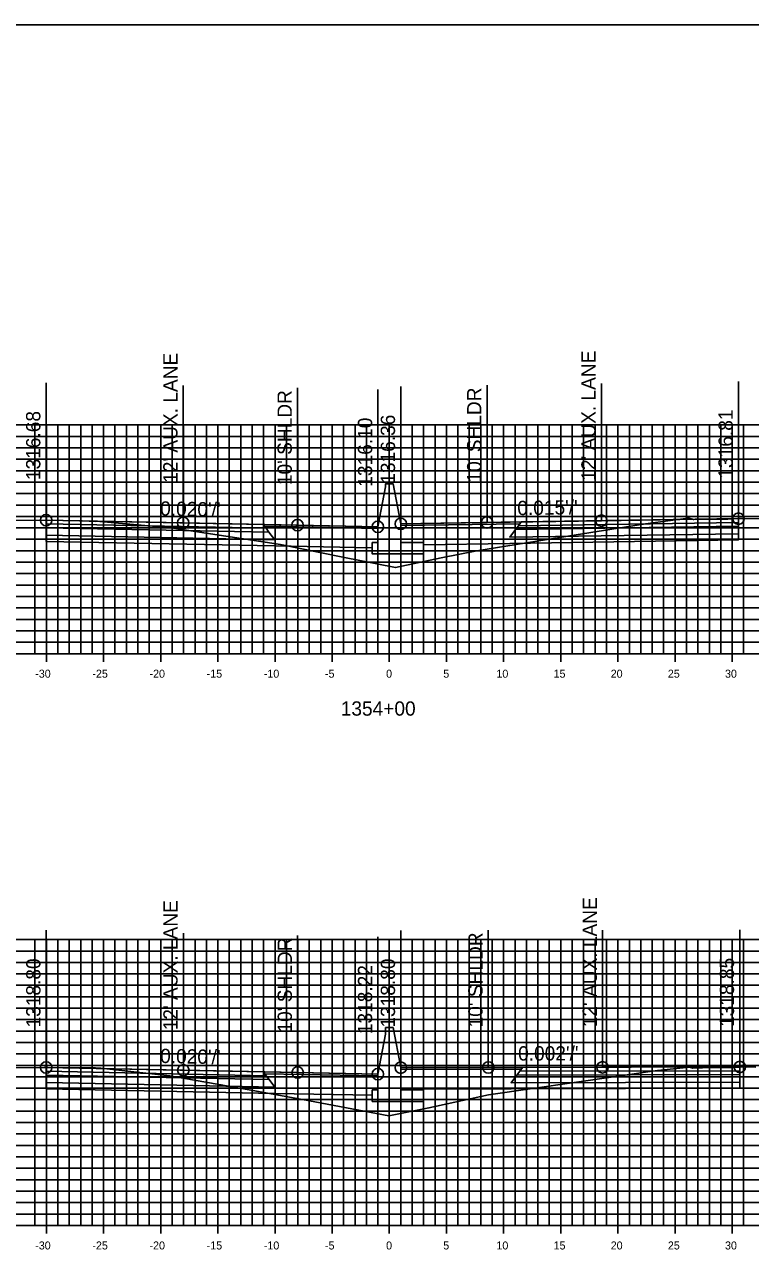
# Model space of a CAD drawing. Extents: x 674939 to 678919, y 750652 to 765176.
# Drawn here: x 678706.6 to 678770.1, y 753564.4 to 753672.6 of the extents above; entities that cross this region are included whole.
import ezdxf

# ---------------------------------------------------------------- set-up
doc = ezdxf.new("R2010")
doc.units = 0
for name, color, linetype in [('R_Alt Surface', 7, 'Continuous'), ('R_Axis', 7, 'Continuous'), ('R_Axis Annot', 7, 'Continuous'), ('R_Exist Surface', 7, 'Continuous'), ('R_Fin Surface', 7, 'Continuous'), ('R_Grid', 7, 'Continuous'), ('R_No Plot', 7, 'Continuous'), ('R_Proposed Road', 7, 'Continuous'), ('R_Xsect Elev', 7, 'Continuous'), ('R_Xsect Slope', 7, 'Continuous')]:
    doc.layers.add(name, color=color, linetype=linetype)

msp = doc.modelspace()

# ---------------------------------------------------------------- linework, layer by layer
at = {"layer": 'R_Alt Surface'}
for points in [[(678708.5, 753628.9), (678708.5, 753628.57), (678728, 753628.18), (678727.75, 753628.52)], [(678769.08, 753628.7), (678769.08, 753628.04), (678749.08, 753627.73), (678749.58, 753628.4)], [(678769.08, 753629.03), (678769.08, 753628.7), (678749.58, 753628.4), (678749.83, 753628.73)], [(678708.5, 753628.57), (678708.5, 753627.91), (678728.5, 753627.51), (678728, 753628.18)], [(678708.51, 753581.03), (678708.51, 753580.7), (678728.01, 753580.31), (678727.76, 753580.64)], [(678769.19, 753581.08), (678769.19, 753580.75), (678749.69, 753580.7), (678749.94, 753581.04)], [(678708.51, 753580.7), (678708.51, 753580.04), (678728.51, 753579.64), (678728.01, 753580.31)], [(678769.19, 753580.75), (678769.19, 753580.09), (678749.19, 753580.03), (678749.69, 753580.7)]]:
    msp.add_lwpolyline(points, close=True, dxfattribs=at)
for points in [[(678708.5, 753627.91), (678708.5, 753627.37), (678728.5, 753626.97), (678737.03, 753626.8)], [(678769.08, 753628.04), (678769.08, 753627.5), (678749.08, 753627.19), (678741.53, 753627.07)], [(678708.51, 753580.04), (678708.51, 753579.5), (678728.51, 753579.1), (678737.03, 753578.93)], [(678769.19, 753580.09), (678769.19, 753579.55), (678749.19, 753579.49), (678741.53, 753579.47)], [(678739.53, 753579.46), (678741.53, 753579.47)]]:
    msp.add_lwpolyline(points, dxfattribs=at)
at = {"layer": 'R_Axis'}
for p, q in [((678708.53, 753616.85), (678708.53, 753618.25)), ((678713.53, 753616.85), (678713.53, 753618.25)), ((678718.53, 753616.85), (678718.53, 753618.25)), ((678723.53, 753616.85), (678723.53, 753618.25)), ((678728.53, 753616.85), (678728.53, 753618.25)), ((678733.53, 753616.85), (678733.53, 753618.25)), ((678738.53, 753616.85), (678738.53, 753618.25)), ((678743.53, 753616.85), (678743.53, 753618.25)), ((678748.53, 753616.85), (678748.53, 753618.25)), ((678753.53, 753616.85), (678753.53, 753618.25)), ((678758.53, 753616.85), (678758.53, 753618.25)), ((678763.53, 753616.85), (678763.53, 753618.25)), ((678768.53, 753616.85), (678768.53, 753618.25)), ((678638.53, 753617.55), (678838.53, 753617.55)), ((678708.53, 753566.85), (678708.53, 753568.25)), ((678713.53, 753566.85), (678713.53, 753568.25)), ((678718.53, 753566.85), (678718.53, 753568.25)), ((678723.53, 753566.85), (678723.53, 753568.25)), ((678728.53, 753566.85), (678728.53, 753568.25)), ((678733.53, 753566.85), (678733.53, 753568.25)), ((678738.53, 753566.85), (678738.53, 753568.25)), ((678743.53, 753566.85), (678743.53, 753568.25)), ((678748.53, 753566.85), (678748.53, 753568.25)), ((678753.53, 753566.85), (678753.53, 753568.25)), ((678758.53, 753566.85), (678758.53, 753568.25)), ((678763.53, 753566.85), (678763.53, 753568.25)), ((678768.53, 753566.85), (678768.53, 753568.25)), ((678638.53, 753567.55), (678838.53, 753567.55))]:
    msp.add_line(p, q, dxfattribs=at)
at = {"layer": 'R_Exist Surface'}
for points in [[(678705.35, 753629.21), (678708.48, 753629.23), (678708.5, 753629.23), (678708.56, 753629.23), (678709.98, 753629.2), (678711.65, 753629.16), (678712.86, 753629.12), (678712.87, 753629.13), (678712.87, 753629.13), (678718.46, 753628.65), (678719.48, 753628.56), (678720.8, 753628.35), (678729, 753627.09), (678734.45, 753626), (678739.07, 753625.08), (678743.06, 753625.92), (678746.19, 753626.55), (678754.88, 753627.95), (678760.94, 753628.9), (678764.43, 753629.36), (678764.63, 753629.39), (678764.64, 753629.39), (678764.75, 753629.39), (678764.75, 753629.39), (678765.14, 753629.28), (678765.16, 753629.28), (678766.9, 753629.32), (678766.95, 753629.32), (678768.1, 753629.32), (678768.15, 753629.32), (678769.05, 753629.36), (678769.08, 753629.36), (678769.1, 753629.36), (678769.55, 753629.38), (678779.94, 753629.16)], [(678705.44, 753581.33), (678708.33, 753581.35), (678708.51, 753581.36), (678708.51, 753581.36), (678708.6, 753581.36), (678708.65, 753581.35), (678709.96, 753581.33), (678710.11, 753581.33), (678712.16, 753581.34), (678712.25, 753581.34), (678712.81, 753581.34), (678713.3, 753581.29), (678719.32, 753580.63), (678723.79, 753579.86), (678726.59, 753579.36), (678730.94, 753578.57), (678738.49, 753577.14), (678741.99, 753577.83), (678747.21, 753578.96), (678758.56, 753580.61), (678761.35, 753581.02), (678761.98, 753581.09), (678764.78, 753581.38), (678764.88, 753581.36), (678765.09, 753581.31), (678765.51, 753581.32), (678765.81, 753581.32), (678765.93, 753581.33), (678766.91, 753581.36), (678767.27, 753581.35), (678767.55, 753581.33), (678768.11, 753581.36), (678768.53, 753581.37), (678768.67, 753581.36), (678769.16, 753581.4), (678769.19, 753581.41), (678769.26, 753581.41), (678769.29, 753581.42), (678770.59, 753581.39)]]:
    msp.add_lwpolyline(points, dxfattribs=at)
at = {"layer": 'R_Fin Surface'}
for points in [[(678737.53, 753628.65), (678730.5, 753628.79), (678720.5, 753628.99), (678708.5, 753629.23)], [(678769.08, 753629.36), (678757.08, 753629.18), (678747.08, 753629.02), (678739.53, 753628.91)], [(678737.53, 753580.78), (678730.51, 753580.92), (678720.51, 753581.12), (678708.51, 753581.36)], [(678769.19, 753581.41), (678757.19, 753581.38), (678747.19, 753581.37), (678739.53, 753581.35)]]:
    msp.add_lwpolyline(points, dxfattribs=at)
for points in [[(678708.5, 753629.23), (678708.5, 753628.9), (678727.75, 753628.52), (678727.5, 753628.85)], [(678727.5, 753628.85), (678737.53, 753628.65), (678737.54, 753628.49), (678727.62, 753628.69)], [(678749.96, 753628.91), (678739.53, 753628.75), (678739.53, 753628.91), (678750.08, 753629.07)], [(678769.08, 753629.36), (678769.08, 753629.03), (678749.83, 753628.73), (678750.08, 753629.07)], [(678708.51, 753581.36), (678708.51, 753581.03), (678727.76, 753580.64), (678727.51, 753580.98)], [(678750.07, 753581.21), (678739.53, 753581.19), (678739.53, 753581.35), (678750.19, 753581.37)], [(678769.19, 753581.41), (678769.19, 753581.08), (678749.94, 753581.04), (678750.19, 753581.37)], [(678727.51, 753580.98), (678737.53, 753580.78), (678737.54, 753580.62), (678727.63, 753580.82)]]:
    msp.add_lwpolyline(points, close=True, dxfattribs=at)
at = {"layer": 'R_Grid'}
for p, q in [((678638.53, 753637.55), (678838.53, 753637.55)), ((678707.53, 753617.55), (678707.53, 753637.55)), ((678708.53, 753617.55), (678708.53, 753637.55)), ((678709.53, 753617.55), (678709.53, 753637.55)), ((678710.53, 753617.55), (678710.53, 753637.55)), ((678711.53, 753617.55), (678711.53, 753637.55)), ((678712.53, 753617.55), (678712.53, 753637.55)), ((678713.53, 753617.55), (678713.53, 753637.55)), ((678714.53, 753617.55), (678714.53, 753637.55)), ((678715.53, 753617.55), (678715.53, 753637.55)), ((678716.53, 753617.55), (678716.53, 753637.55)), ((678717.53, 753617.55), (678717.53, 753637.55)), ((678718.53, 753617.55), (678718.53, 753637.55)), ((678719.53, 753617.55), (678719.53, 753637.55)), ((678720.53, 753617.55), (678720.53, 753637.55)), ((678721.53, 753617.55), (678721.53, 753637.55)), ((678722.53, 753617.55), (678722.53, 753637.55)), ((678723.53, 753617.55), (678723.53, 753637.55)), ((678724.53, 753617.55), (678724.53, 753637.55)), ((678725.53, 753617.55), (678725.53, 753637.55)), ((678726.53, 753617.55), (678726.53, 753637.55)), ((678727.53, 753617.55), (678727.53, 753637.55)), ((678728.53, 753617.55), (678728.53, 753637.55)), ((678729.53, 753617.55), (678729.53, 753637.55)), ((678730.53, 753617.55), (678730.53, 753637.55)), ((678731.53, 753617.55), (678731.53, 753637.55)), ((678732.53, 753617.55), (678732.53, 753637.55)), ((678733.53, 753617.55), (678733.53, 753637.55)), ((678734.53, 753617.55), (678734.53, 753637.55)), ((678735.53, 753617.55), (678735.53, 753637.55)), ((678736.53, 753617.55), (678736.53, 753637.55)), ((678737.53, 753617.55), (678737.53, 753637.55)), ((678738.53, 753617.55), (678738.53, 753637.55)), ((678739.53, 753617.55), (678739.53, 753637.55)), ((678740.53, 753617.55), (678740.53, 753637.55)), ((678741.53, 753617.55), (678741.53, 753637.55)), ((678742.53, 753617.55), (678742.53, 753637.55)), ((678743.53, 753617.55), (678743.53, 753637.55)), ((678744.53, 753617.55), (678744.53, 753637.55)), ((678745.53, 753617.55), (678745.53, 753637.55)), ((678746.53, 753617.55), (678746.53, 753637.55)), ((678747.53, 753617.55), (678747.53, 753637.55)), ((678748.53, 753617.55), (678748.53, 753637.55)), ((678749.53, 753617.55), (678749.53, 753637.55)), ((678750.53, 753617.55), (678750.53, 753637.55)), ((678751.53, 753617.55), (678751.53, 753637.55)), ((678752.53, 753617.55), (678752.53, 753637.55)), ((678753.53, 753617.55), (678753.53, 753637.55)), ((678754.53, 753617.55), (678754.53, 753637.55)), ((678755.53, 753617.55), (678755.53, 753637.55)), ((678756.53, 753617.55), (678756.53, 753637.55)), ((678757.53, 753617.55), (678757.53, 753637.55)), ((678758.53, 753617.55), (678758.53, 753637.55)), ((678759.53, 753617.55), (678759.53, 753637.55)), ((678760.53, 753617.55), (678760.53, 753637.55)), ((678761.53, 753617.55), (678761.53, 753637.55)), ((678762.53, 753617.55), (678762.53, 753637.55)), ((678763.53, 753617.55), (678763.53, 753637.55)), ((678764.53, 753617.55), (678764.53, 753637.55)), ((678765.53, 753617.55), (678765.53, 753637.55)), ((678766.53, 753617.55), (678766.53, 753637.55)), ((678767.53, 753617.55), (678767.53, 753637.55)), ((678768.53, 753617.55), (678768.53, 753637.55)), ((678769.53, 753617.55), (678769.53, 753637.55)), ((678638.53, 753636.55), (678838.53, 753636.55)), ((678638.53, 753635.55), (678838.53, 753635.55)), ((678638.53, 753634.55), (678838.53, 753634.55)), ((678638.53, 753633.55), (678838.53, 753633.55)), ((678638.53, 753632.55), (678838.53, 753632.55)), ((678638.53, 753631.55), (678838.53, 753631.55)), ((678638.53, 753630.55), (678838.53, 753630.55)), ((678638.53, 753629.55), (678838.53, 753629.55)), ((678638.53, 753628.55), (678838.53, 753628.55)), ((678638.53, 753627.55), (678838.53, 753627.55)), ((678638.53, 753626.55), (678838.53, 753626.55)), ((678638.53, 753625.55), (678838.53, 753625.55)), ((678638.53, 753624.55), (678838.53, 753624.55)), ((678638.53, 753623.55), (678838.53, 753623.55)), ((678638.53, 753622.55), (678838.53, 753622.55)), ((678638.53, 753621.55), (678838.53, 753621.55)), ((678638.53, 753620.55), (678838.53, 753620.55)), ((678638.53, 753619.55), (678838.53, 753619.55)), ((678638.53, 753618.55), (678838.53, 753618.55)), ((678638.53, 753617.55), (678838.53, 753617.55)), ((678638.53, 753592.55), (678838.53, 753592.55)), ((678707.53, 753567.55), (678707.53, 753592.55)), ((678708.53, 753567.55), (678708.53, 753592.55)), ((678709.53, 753567.55), (678709.53, 753592.55)), ((678710.53, 753567.55), (678710.53, 753592.55)), ((678711.53, 753567.55), (678711.53, 753592.55)), ((678712.53, 753567.55), (678712.53, 753592.55)), ((678713.53, 753567.55), (678713.53, 753592.55)), ((678714.53, 753567.55), (678714.53, 753592.55)), ((678715.53, 753567.55), (678715.53, 753592.55)), ((678716.53, 753567.55), (678716.53, 753592.55)), ((678717.53, 753567.55), (678717.53, 753592.55)), ((678718.53, 753567.55), (678718.53, 753592.55)), ((678719.53, 753567.55), (678719.53, 753592.55)), ((678720.53, 753567.55), (678720.53, 753592.55)), ((678721.53, 753567.55), (678721.53, 753592.55)), ((678722.53, 753567.55), (678722.53, 753592.55)), ((678723.53, 753567.55), (678723.53, 753592.55)), ((678724.53, 753567.55), (678724.53, 753592.55)), ((678725.53, 753567.55), (678725.53, 753592.55)), ((678726.53, 753567.55), (678726.53, 753592.55)), ((678727.53, 753567.55), (678727.53, 753592.55)), ((678728.53, 753567.55), (678728.53, 753592.55)), ((678729.53, 753567.55), (678729.53, 753592.55)), ((678730.53, 753567.55), (678730.53, 753592.55)), ((678731.53, 753567.55), (678731.53, 753592.55)), ((678732.53, 753567.55), (678732.53, 753592.55)), ((678733.53, 753567.55), (678733.53, 753592.55)), ((678734.53, 753567.55), (678734.53, 753592.55)), ((678735.53, 753567.55), (678735.53, 753592.55)), ((678736.53, 753567.55), (678736.53, 753592.55)), ((678737.53, 753567.55), (678737.53, 753592.55)), ((678738.53, 753567.55), (678738.53, 753592.55)), ((678739.53, 753567.55), (678739.53, 753592.55)), ((678740.53, 753567.55), (678740.53, 753592.55)), ((678741.53, 753567.55), (678741.53, 753592.55)), ((678742.53, 753567.55), (678742.53, 753592.55)), ((678743.53, 753567.55), (678743.53, 753592.55)), ((678744.53, 753567.55), (678744.53, 753592.55)), ((678745.53, 753567.55), (678745.53, 753592.55)), ((678746.53, 753567.55), (678746.53, 753592.55)), ((678747.53, 753567.55), (678747.53, 753592.55)), ((678748.53, 753567.55), (678748.53, 753592.55)), ((678749.53, 753567.55), (678749.53, 753592.55)), ((678750.53, 753567.55), (678750.53, 753592.55)), ((678751.53, 753567.55), (678751.53, 753592.55)), ((678752.53, 753567.55), (678752.53, 753592.55)), ((678753.53, 753567.55), (678753.53, 753592.55)), ((678754.53, 753567.55), (678754.53, 753592.55)), ((678755.53, 753567.55), (678755.53, 753592.55)), ((678756.53, 753567.55), (678756.53, 753592.55)), ((678757.53, 753567.55), (678757.53, 753592.55)), ((678758.53, 753567.55), (678758.53, 753592.55)), ((678759.53, 753567.55), (678759.53, 753592.55)), ((678760.53, 753567.55), (678760.53, 753592.55)), ((678761.53, 753567.55), (678761.53, 753592.55)), ((678762.53, 753567.55), (678762.53, 753592.55)), ((678763.53, 753567.55), (678763.53, 753592.55)), ((678764.53, 753567.55), (678764.53, 753592.55)), ((678765.53, 753567.55), (678765.53, 753592.55)), ((678766.53, 753567.55), (678766.53, 753592.55)), ((678767.53, 753567.55), (678767.53, 753592.55)), ((678768.53, 753567.55), (678768.53, 753592.55)), ((678769.53, 753567.55), (678769.53, 753592.55)), ((678638.53, 753591.55), (678838.53, 753591.55)), ((678638.53, 753590.55), (678838.53, 753590.55)), ((678638.53, 753589.55), (678838.53, 753589.55)), ((678638.53, 753588.55), (678838.53, 753588.55)), ((678638.53, 753587.55), (678838.53, 753587.55)), ((678638.53, 753586.55), (678838.53, 753586.55)), ((678638.53, 753585.55), (678838.53, 753585.55)), ((678638.53, 753584.55), (678838.53, 753584.55)), ((678638.53, 753583.55), (678838.53, 753583.55)), ((678638.53, 753582.55), (678838.53, 753582.55)), ((678638.53, 753581.55), (678838.53, 753581.55)), ((678638.53, 753580.55), (678838.53, 753580.55)), ((678638.53, 753579.55), (678838.53, 753579.55)), ((678638.53, 753578.55), (678838.53, 753578.55)), ((678638.53, 753577.55), (678838.53, 753577.55)), ((678638.53, 753576.55), (678838.53, 753576.55)), ((678638.53, 753575.55), (678838.53, 753575.55)), ((678638.53, 753574.55), (678838.53, 753574.55)), ((678638.53, 753573.55), (678838.53, 753573.55)), ((678638.53, 753572.55), (678838.53, 753572.55)), ((678638.53, 753571.55), (678838.53, 753571.55)), ((678638.53, 753570.55), (678838.53, 753570.55)), ((678638.53, 753569.55), (678838.53, 753569.55)), ((678638.53, 753568.55), (678838.53, 753568.55)), ((678638.53, 753567.55), (678838.53, 753567.55))]:
    msp.add_line(p, q, dxfattribs=at)
at = {"layer": 'R_No Plot'}
msp.add_lwpolyline([(678578.53, 753452.55), (678918.53, 753452.55), (678918.53, 753672.55), (678578.53, 753672.55)], close=True, dxfattribs=at)
for centre in [(678708.5, 753629.23), (678769.08, 753629.36), (678720.5, 753628.99), (678730.5, 753628.79), (678737.53, 753628.65), (678739.53, 753628.91), (678747.08, 753629.02), (678757.08, 753629.18), (678708.51, 753581.36), (678720.51, 753581.12), (678730.51, 753580.92), (678737.53, 753580.78), (678739.53, 753581.35), (678747.19, 753581.37), (678757.19, 753581.38), (678769.19, 753581.41)]:
    msp.add_circle(centre, 0.5, dxfattribs=at)
at = {"layer": 'R_Proposed Road'}
for points in [[(678738.2, 753632.15), (678737.53, 753628.65)], [(678738.86, 753632.41), (678738.86, 753632.41), (678738.2, 753632.41), (678738.2, 753632.15)], [(678738.86, 753632.41), (678739.53, 753628.91)], [(678737.53, 753628.65), (678737.53, 753627.27), (678737.03, 753627.27), (678737.03, 753626.27), (678741.53, 753626.27), (678741.53, 753627.27), (678739.53, 753627.27), (678739.53, 753628.91)], [(678738.2, 753584.28), (678737.53, 753580.78)], [(678738.86, 753584.85), (678738.86, 753584.85), (678738.2, 753584.85), (678738.2, 753584.28)], [(678738.86, 753584.85), (678739.53, 753581.35)], [(678737.53, 753580.78), (678737.53, 753579.4), (678737.03, 753579.4), (678737.03, 753578.4), (678741.53, 753578.4), (678741.53, 753579.4), (678739.53, 753579.4), (678739.53, 753581.35)]]:
    msp.add_lwpolyline(points, dxfattribs=at)
at = {"layer": 'R_Xsect Elev'}
for p, q in [((678708.5, 753629.23), (678708.5, 753641.23)), ((678720.5, 753628.99), (678720.5, 753640.99)), ((678730.5, 753628.79), (678730.5, 753640.79)), ((678737.53, 753628.65), (678737.53, 753640.65)), ((678739.53, 753628.91), (678739.53, 753640.91)), ((678747.08, 753629.02), (678747.08, 753641.02)), ((678757.08, 753629.18), (678757.08, 753641.18)), ((678769.08, 753629.36), (678769.08, 753641.36)), ((678708.51, 753581.36), (678708.51, 753593.36)), ((678720.51, 753581.12), (678720.51, 753593.12)), ((678739.53, 753581.35), (678739.53, 753593.35)), ((678747.19, 753581.37), (678747.19, 753593.37)), ((678757.19, 753581.38), (678757.19, 753593.38)), ((678769.19, 753581.41), (678769.19, 753593.41)), ((678730.51, 753580.92), (678730.51, 753592.92)), ((678737.53, 753580.78), (678737.53, 753592.78))]:
    msp.add_line(p, q, dxfattribs=at)

# ---------------------------------------------------------------- texts
at = {"layer": 'R_Axis Annot'}
for s, height, p in [('-30', 0.7, (678707.55, 753615.45)), ('-25', 0.7, (678712.55, 753615.45)), ('-20', 0.7, (678717.55, 753615.45)), ('-15', 0.7, (678722.55, 753615.45)), ('-10', 0.7, (678727.55, 753615.45)), ('-5', 0.7, (678732.9, 753615.45)), ('0', 0.7, (678738.25, 753615.45)), ('5', 0.7, (678743.25, 753615.45)), ('10', 0.7, (678747.9, 753615.45)), ('15', 0.7, (678752.9, 753615.45)), ('20', 0.7, (678757.9, 753615.45)), ('25', 0.7, (678762.9, 753615.45)), ('30', 0.7, (678767.9, 753615.45)), ('1354+00', 1.25, (678734.28, 753612.13)), ('-30', 0.7, (678707.55, 753565.45)), ('-25', 0.7, (678712.55, 753565.45)), ('-20', 0.7, (678717.55, 753565.45)), ('-15', 0.7, (678722.55, 753565.45)), ('-10', 0.7, (678727.55, 753565.45)), ('-5', 0.7, (678732.9, 753565.45)), ('0', 0.7, (678738.25, 753565.45)), ('5', 0.7, (678743.25, 753565.45)), ('10', 0.7, (678747.9, 753565.45)), ('15', 0.7, (678752.9, 753565.45)), ('20', 0.7, (678757.9, 753565.45)), ('25', 0.7, (678762.9, 753565.45)), ('30', 0.7, (678767.9, 753565.45))]:
    msp.add_text(s, height=height, dxfattribs=at).set_placement(p)
at = {"layer": 'R_Xsect Elev'}
for s, p in [("12' AUX. LANE", (678720, 753632.49)), ("12' AUX. LANE", (678756.58, 753632.68)), ("10' SHLDR", (678730, 753632.29)), ("10' SHLDR", (678746.58, 753632.52)), ('1316.68', (678708, 753632.73)), ('1316.36', (678739.03, 753632.41)), ('1316.81', (678768.58, 753632.86)), ('1316.10', (678737.03, 753632.15)), ("12' AUX. LANE", (678756.69, 753584.88)), ("12' AUX. LANE", (678720.01, 753584.62)), ("10' SHLDR", (678746.69, 753584.87)), ("10' SHLDR", (678730.01, 753584.42)), ('1318.80', (678708.01, 753584.86)), ('1318.80', (678739.03, 753584.85)), ('1318.85', (678768.69, 753584.91)), ('1318.22', (678737.03, 753584.28))]:
    msp.add_text(s, height=1.25, rotation=90, dxfattribs=at).set_placement(p)
at = {"layer": 'R_Xsect Slope'}
for s, rotation, p in [("0.020'/'", 358.8542, (678718.47, 753629.63)), ("0.015'/'", 0.8691, (678749.74, 753629.66)), ("0.002'/'", 0.1053, (678749.8, 753581.97)), ("0.020'/'", 358.8542, (678718.47, 753581.76))]:
    msp.add_text(s, height=1.25, rotation=rotation, dxfattribs=at).set_placement(p)

doc.saveas('drawing.dxf')
